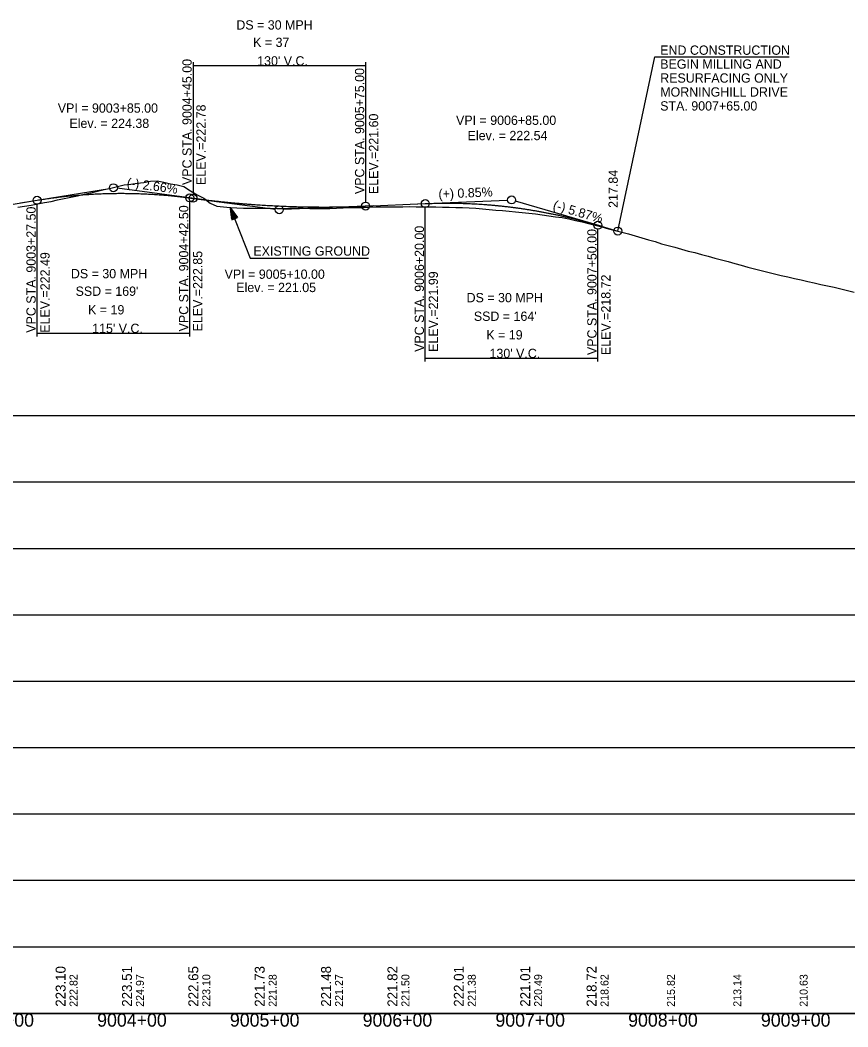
# Model space of a CAD drawing. Extents: x 69 to 2003113, y 512 to 837401.
# Drawn here: x 1878004 to 1878627, y 765979 to 766737 of the extents above; entities that cross this region are included whole.
import ezdxf

# ---------------------------------------------------------------- set-up
doc = ezdxf.new("R2010")
doc.units = 0
for name, color, linetype in [('BR_AUTO DIMENSION', 7, 'Continuous'), ('BR_CENTER LINE BASELINE', 7, 'Continuous'), ('BR_CONCRETE', 7, 'Continuous'), ('BR_GRID DOTS', 7, 'Continuous'), ('BR_GRID LINES', 7, 'Continuous'), ('BR_TEXT', 7, 'Continuous'), ('Default', 7, 'Continuous'), ('RD_HC_Points', 7, 'Continuous'), ('RD_PD_ALT1_TrvlWay', 7, 'Continuous'), ('RD_SHT_ID', 7, 'Continuous'), ('RD_SHT_IplotShp', 7, 'Continuous')]:
    doc.layers.add(name, color=color, linetype=linetype)

msp = doc.modelspace()

# ---------------------------------------------------------------- linework, layer by layer
at = {"layer": 'BR_AUTO DIMENSION'}
for p, q in [((1880911.61, 766439.14), (1877507.29, 766439.14)), ((1880911.61, 766389.14), (1877507.29, 766389.14)), ((1880911.61, 766339.14), (1877507.29, 766339.14)), ((1880911.61, 766289.14), (1877507.29, 766289.14)), ((1880911.61, 766239.14), (1877507.29, 766239.14)), ((1880911.61, 766189.14), (1877507.29, 766189.14)), ((1880911.61, 766139.14), (1877507.29, 766139.14)), ((1880911.61, 766089.14), (1877507.29, 766089.14)), ((1880911.61, 766039.14), (1877507.29, 766039.14)), ((1880911.61, 765989.14), (1877507.29, 765989.14))]:
    msp.add_line(p, q, dxfattribs=at)
at = {"layer": 'BR_CENTER LINE BASELINE'}
for p, q in [((1878003.69, 766599.52), (1878070.79, 766610.55)), ((1878144.13, 766601.67), (1878076.73, 766610.64)), ((1878128.37, 766603.77), (1878195.78, 766594.8)), ((1878302.82, 766598.83), (1878370.76, 766601.71)), ((1878441.88, 766581.83), (1878376.63, 766600.99)), ((1878269.69, 766597.42), (1878201.75, 766594.54))]:
    msp.add_line(p, q, dxfattribs=at)
for centre in [(1878073.75, 766611.03), (1878373.75, 766601.84), (1878198.75, 766594.41), (1878453.75, 766578.34)]:
    msp.add_circle(centre, 3, dxfattribs=at)
at = {"layer": 'BR_GRID DOTS'}
for p, q in [((1878453.75, 766578.34), (1878481.71, 766709.65)), ((1878133.75, 766705.55), (1878133.75, 766606.05)), ((1878133.75, 766703.05), (1878263.75, 766703.05)), ((1878263.75, 766705.55), (1878263.75, 766600.17)), ((1878016.25, 766499.09), (1878016.25, 766598.59)), ((1878131.25, 766499.09), (1878131.25, 766600.39)), ((1878308.75, 766480.24), (1878308.75, 766596.08)), ((1878438.75, 766480.24), (1878438.75, 766579.74)), ((1878016.25, 766501.59), (1878131.25, 766501.59)), ((1878308.75, 766482.74), (1878438.75, 766482.74))]:
    msp.add_line(p, q, dxfattribs=at)
msp.add_lwpolyline([(1878481.71, 766709.65), (1878582.93, 766709.65)], dxfattribs=at)
for centre in [(1878016.25, 766601.59), (1878131.25, 766603.39), (1878133.75, 766603.05), (1878308.75, 766599.08), (1878263.75, 766597.17), (1878438.75, 766582.74)]:
    msp.add_circle(centre, 3, dxfattribs=at)
at = {"layer": 'BR_GRID LINES'}
for p, q in [((1877993.75, 766597.89), (1878016.25, 766601.59)), ((1878131.25, 766603.39), (1878133.75, 766603.05)), ((1878263.75, 766597.17), (1878308.75, 766599.08)), ((1878438.75, 766582.74), (1878453.75, 766578.34))]:
    msp.add_line(p, q, dxfattribs=at)
for points in [[(1878016.25, 766601.59), (1878018.55, 766601.96), (1878020.85, 766602.31), (1878023.15, 766602.66), (1878025.45, 766602.99), (1878027.75, 766603.3), (1878030.05, 766603.61), (1878032.35, 766603.9), (1878034.65, 766604.17), (1878036.95, 766604.43), (1878039.25, 766604.68), (1878041.55, 766604.92), (1878043.85, 766605.14), (1878046.15, 766605.34), (1878048.45, 766605.54), (1878050.75, 766605.72), (1878053.05, 766605.88), (1878055.35, 766606.03), (1878057.65, 766606.17), (1878059.95, 766606.3), (1878062.25, 766606.41), (1878064.55, 766606.51), (1878066.85, 766606.59), (1878069.15, 766606.66), (1878071.45, 766606.72), (1878073.75, 766606.76), (1878076.05, 766606.79), (1878078.35, 766606.81), (1878080.65, 766606.81), (1878082.95, 766606.79), (1878085.25, 766606.77), (1878087.55, 766606.73), (1878089.85, 766606.68), (1878092.15, 766606.61), (1878094.45, 766606.53), (1878096.75, 766606.44), (1878099.05, 766606.33), (1878101.35, 766606.21), (1878103.65, 766606.07), (1878105.95, 766605.92), (1878108.25, 766605.76), (1878110.55, 766605.59), (1878112.85, 766605.4), (1878115.15, 766605.19), (1878117.45, 766604.98), (1878119.75, 766604.74), (1878122.05, 766604.5), (1878124.35, 766604.24), (1878126.65, 766603.97), (1878128.95, 766603.69), (1878131.25, 766603.39)], [(1878133.75, 766603.05), (1878136.35, 766602.71), (1878138.95, 766602.38), (1878141.55, 766602.06), (1878144.15, 766601.74), (1878146.75, 766601.44), (1878149.35, 766601.14), (1878151.95, 766600.86), (1878154.55, 766600.58), (1878157.15, 766600.31), (1878159.75, 766600.05), (1878162.35, 766599.8), (1878164.95, 766599.56), (1878167.55, 766599.33), (1878170.15, 766599.11), (1878172.75, 766598.89), (1878175.35, 766598.69), (1878177.95, 766598.49), (1878180.55, 766598.31), (1878183.15, 766598.13), (1878185.75, 766597.96), (1878188.35, 766597.8), (1878190.95, 766597.65), (1878193.55, 766597.51), (1878196.15, 766597.38), (1878198.75, 766597.26), (1878201.35, 766597.15), (1878203.95, 766597.04), (1878206.55, 766596.95), (1878209.15, 766596.86), (1878211.75, 766596.78), (1878214.35, 766596.72), (1878216.95, 766596.66), (1878219.55, 766596.61), (1878222.15, 766596.57), (1878224.75, 766596.54), (1878227.35, 766596.52), (1878229.95, 766596.5), (1878232.55, 766596.5), (1878235.15, 766596.5), (1878237.75, 766596.52), (1878240.35, 766596.54), (1878242.95, 766596.58), (1878245.55, 766596.62), (1878248.15, 766596.67), (1878250.75, 766596.73), (1878253.35, 766596.8), (1878255.95, 766596.88), (1878258.55, 766596.96), (1878261.15, 766597.06), (1878263.75, 766597.17)], [(1878308.75, 766599.08), (1878311.35, 766599.18), (1878313.95, 766599.26), (1878316.55, 766599.33), (1878319.15, 766599.38), (1878321.75, 766599.41), (1878324.35, 766599.42), (1878326.95, 766599.42), (1878329.55, 766599.4), (1878332.15, 766599.36), (1878334.75, 766599.31), (1878337.35, 766599.23), (1878339.95, 766599.14), (1878342.55, 766599.03), (1878345.15, 766598.91), (1878347.75, 766598.77), (1878350.35, 766598.61), (1878352.95, 766598.43), (1878355.55, 766598.23), (1878358.15, 766598.02), (1878360.75, 766597.79), (1878363.35, 766597.54), (1878365.95, 766597.27), (1878368.55, 766596.99), (1878371.15, 766596.69), (1878373.75, 766596.37), (1878376.35, 766596.04), (1878378.95, 766595.69), (1878381.55, 766595.31), (1878384.15, 766594.93), (1878386.75, 766594.52), (1878389.35, 766594.1), (1878391.95, 766593.66), (1878394.55, 766593.2), (1878397.15, 766592.73), (1878399.75, 766592.23), (1878402.35, 766591.72), (1878404.95, 766591.2), (1878407.55, 766590.65), (1878410.15, 766590.09), (1878412.75, 766589.51), (1878415.35, 766588.91), (1878417.95, 766588.29), (1878420.55, 766587.66), (1878423.15, 766587.01), (1878425.75, 766586.34), (1878428.35, 766585.66), (1878430.95, 766584.96), (1878433.55, 766584.24), (1878436.15, 766583.5), (1878438.75, 766582.74)]]:
    msp.add_spline(points, degree=3, dxfattribs=at)
at = {"layer": 'BR_TEXT'}
for points in [[(1878001.79, 766596.29), (1878006.79, 766597.13), (1878011.79, 766597.96), (1878016.79, 766598.87), (1878021.79, 766599.81), (1878026.79, 766600.74), (1878031.79, 766601.78), (1878036.79, 766602.84), (1878041.79, 766603.89), (1878046.79, 766604.95), (1878051.79, 766606.09), (1878056.79, 766607.25), (1878061.79, 766608.42), (1878066.79, 766609.65), (1878071.79, 766610.8), (1878076.79, 766611.99), (1878081.79, 766613.15), (1878086.79, 766613.74), (1878091.79, 766614.35), (1878096.79, 766615.02), (1878101.79, 766615.85), (1878106.79, 766616.17), (1878111.79, 766615.18), (1878116.79, 766613.94), (1878121.79, 766613.2), (1878126.79, 766612), (1878131.79, 766608.74), (1878136.79, 766605.58), (1878141.79, 766603.15), (1878146.79, 766599.49), (1878151.79, 766597.22), (1878156.79, 766596.53), (1878161.79, 766596.04), (1878166.79, 766595.84), (1878171.79, 766595.64), (1878176.79, 766595.62), (1878181.79, 766595.67), (1878186.79, 766595.6), (1878191.79, 766595.52), (1878196.79, 766595.45), (1878201.79, 766595.46), (1878206.79, 766595.59), (1878211.79, 766595.62), (1878216.79, 766595.53), (1878221.79, 766595.43), (1878226.79, 766595.38), (1878231.79, 766595.38), (1878236.79, 766595.37), (1878241.79, 766595.66), (1878246.79, 766595.97), (1878251.79, 766596.09), (1878256.79, 766596.06)], [(1878256.79, 766596.06), (1878261.79, 766596.03), (1878266.79, 766596.31), (1878271.79, 766596.56), (1878276.79, 766596.54), (1878281.79, 766596.51), (1878286.79, 766596.62), (1878291.79, 766596.75), (1878296.79, 766596.79), (1878301.79, 766596.69), (1878306.79, 766596.59), (1878311.79, 766596.67), (1878316.79, 766596.57), (1878321.79, 766596.41), (1878326.79, 766596.28), (1878331.79, 766596.18), (1878336.79, 766596.08), (1878341.79, 766595.94), (1878346.79, 766595.72), (1878351.79, 766595.2), (1878356.79, 766594.68), (1878361.79, 766594.17), (1878366.79, 766593.81), (1878371.79, 766593.46), (1878376.79, 766592.9), (1878381.79, 766592.31), (1878386.79, 766591.78), (1878391.79, 766591.27), (1878396.79, 766590.66), (1878401.79, 766589.83), (1878406.79, 766589.08), (1878411.79, 766588.57), (1878416.79, 766587.52), (1878421.79, 766586.3), (1878426.79, 766585.22), (1878431.79, 766584.07), (1878436.79, 766582.78), (1878441.79, 766581.48), (1878446.79, 766580.17), (1878451.79, 766578.85), (1878456.79, 766577.54), (1878461.79, 766576.18), (1878466.79, 766574.71), (1878471.79, 766573.26), (1878476.79, 766571.83), (1878481.79, 766570.4), (1878486.79, 766568.76), (1878491.79, 766567.43), (1878496.79, 766566.14), (1878501.79, 766564.72), (1878506.79, 766563.36), (1878511.79, 766562.12), (1878516.79, 766560.84), (1878521.79, 766559.43), (1878526.79, 766558.03), (1878531.79, 766556.69), (1878536.79, 766555.38), (1878541.79, 766554.05), (1878546.79, 766552.65), (1878551.79, 766551.25), (1878556.79, 766549.86), (1878561.79, 766548.58), (1878566.79, 766547.35), (1878571.79, 766546.16), (1878576.79, 766545.02), (1878581.79, 766543.88), (1878586.79, 766542.74), (1878591.79, 766541.61), (1878596.79, 766540.47), (1878601.79, 766539.34), (1878606.79, 766538.2), (1878611.79, 766537.1), (1878616.79, 766536.04), (1878621.79, 766534.91), (1878626.79, 766533.69), (1878631.79, 766532.47)]]:
    msp.add_lwpolyline(points, dxfattribs=at)
at = {"layer": 'Default'}
msp.add_line((1877688.75, 765989.14), (1880688.75, 765989.14), dxfattribs=at)
at = {"layer": 'RD_PD_ALT1_TrvlWay'}
for p, q in [((1878161.79, 766596.04), (1878176.76, 766558.09)), ((1878165.09, 766587.67), (1878161.79, 766596.04)), ((1878161.79, 766596.04), (1878167.19, 766588.49)), ((1878161.79, 766596.04), (1878163, 766586.84)), ((1878163, 766586.84), (1878167.19, 766588.49)), ((1878176.76, 766558.09), (1878265.94, 766558.09))]:
    msp.add_line(p, q, dxfattribs=at)
for points in [[(1878164.99, 766587.75), (1878161.92, 766595.55), (1878164.96, 766587.68), (1878161.99, 766595.15), (1878164.86, 766587.68), (1878162.02, 766594.88), (1878164.75, 766587.65), (1878162.05, 766594.56), (1878164.67, 766587.6), (1878162.12, 766594.06), (1878164.56, 766587.54), (1878162.21, 766593.54), (1878164.44, 766587.53), (1878162.27, 766593.14), (1878164.36, 766587.48), (1878162.33, 766592.68), (1878164.25, 766587.5), (1878162.38, 766592.29), (1878164.19, 766587.39), (1878162.42, 766591.94), (1878164.06, 766587.38), (1878162.48, 766591.44), (1878163.96, 766587.32), (1878162.59, 766590.85), (1878163.86, 766587.26), (1878162.6, 766590.43), (1878163.76, 766587.22), (1878162.68, 766589.8), (1878163.64, 766587.22), (1878162.78, 766589.3), (1878163.54, 766587.12), (1878162.83, 766588.86), (1878163.44, 766587.12), (1878162.87, 766588.46), (1878163.36, 766587.02), (1878162.95, 766587.96), (1878163.24, 766587.06), (1878163.02, 766587.41), (1878163.13, 766587.05)], [(1878162.07, 766595.52), (1878165.11, 766587.8), (1878162.23, 766595.27), (1878165.22, 766587.84), (1878162.38, 766595.03), (1878165.3, 766587.83), (1878162.57, 766594.82), (1878165.36, 766587.88), (1878162.77, 766594.56), (1878165.46, 766587.89), (1878162.95, 766594.31), (1878165.53, 766587.92), (1878163.16, 766594.01), (1878165.62, 766587.94), (1878163.41, 766593.65), (1878165.73, 766588), (1878163.61, 766593.33), (1878165.82, 766587.99), (1878163.84, 766593), (1878165.9, 766588.05), (1878164.08, 766592.7), (1878165.98, 766588.08), (1878164.32, 766592.35), (1878166.03, 766588.16), (1878164.64, 766591.89), (1878166.13, 766588.16), (1878164.87, 766591.61), (1878166.21, 766588.15), (1878165.17, 766591.22), (1878166.29, 766588.22), (1878165.41, 766590.81), (1878166.38, 766588.28), (1878165.63, 766590.5), (1878166.47, 766588.37), (1878165.88, 766590.22), (1878166.54, 766588.4), (1878166.16, 766589.75), (1878166.69, 766588.38), (1878166.35, 766589.49), (1878166.82, 766588.43), (1878166.54, 766589.32), (1878166.93, 766588.57), (1878167.05, 766588.52), (1878166.89, 766588.56)]]:
    msp.add_lwpolyline(points, dxfattribs=at)

# ---------------------------------------------------------------- texts
at = {"layer": 'BR_CENTER LINE BASELINE'}
for s, rotation, p in [('(-) 2.66%', 352.4233, (1878083.61, 766611.5)), ('(+) 0.85%', 2.43062, (1878318.79, 766602.76)), ('(-) 5.87%', 343.63166, (1878404.34, 766594.94))]:
    msp.add_text(s, height=7, rotation=rotation, dxfattribs=at).set_placement(p)
at = {"layer": 'BR_CONCRETE'}
for s, height, p in [('VPC STA. 9004+45.00 ', 7, (1878132.75, 766613.05)), ('VPC STA. 9005+75.00 ', 7, (1878262.75, 766606.22)), ('ELEV.=222.78', 7, (1878143.25, 766613.05)), ('ELEV.=221.60', 7, (1878273.25, 766606.22)), ('VPC STA. 9003+27.50 ', 7, (1878015.25, 766501.81)), ('VPC STA. 9004+42.50 ', 7, (1878130.25, 766502.81)), ('VPC STA. 9006+20.00 ', 7, (1878307.75, 766487.39)), ('VPC STA. 9007+50.00 ', 7, (1878437.75, 766484.98)), ('ELEV.=222.85', 7, (1878140.75, 766502.81)), ('ELEV.=222.49', 7, (1878025.75, 766501.81)), ('ELEV.=221.99', 7, (1878318.25, 766487.39)), ('ELEV.=218.72', 7, (1878448.25, 766484.98)), ('222.82', 6, (1878046.75, 765994.14)), ('224.97', 6, (1878096.75, 765994.14)), ('223.10', 6, (1878146.75, 765994.14)), ('221.28', 6, (1878196.75, 765994.14)), ('221.27', 6, (1878246.75, 765994.14)), ('221.50', 6, (1878296.75, 765994.14)), ('221.38', 6, (1878346.75, 765994.14)), ('220.49', 6, (1878396.75, 765994.14)), ('218.62', 6, (1878446.75, 765994.14)), ('215.82', 6, (1878496.75, 765994.14)), ('213.14', 6, (1878546.75, 765994.14)), ('210.63', 6, (1878596.75, 765994.14))]:
    msp.add_text(s, height=height, rotation=90, dxfattribs=at).set_placement(p)
at = {"layer": 'BR_GRID DOTS'}
for s, p in [('DS = 30 MPH', (1878166.4, 766730.14)), ('K = 37', (1878179.03, 766717.05)), ("130' V.C.", (1878182.11, 766703.05)), ('DS = 30 MPH', (1878041.76, 766542.83)), ("SSD = 169'", (1878045.3, 766529.59)), ('DS = 30 MPH', (1878339.85, 766524.75)), ('K = 19', (1878054.72, 766515.59)), ("SSD = 164'", (1878345.3, 766510.74)), ("115' V.C.", (1878057.78, 766501.59)), ('K = 19', (1878354.72, 766496.74)), ("130' V.C.", (1878357.11, 766482.74))]:
    msp.add_text(s, height=7, dxfattribs=at).set_placement(p)
at = {"layer": 'RD_HC_Points'}
for s, p in [('223.10', (1878037.75, 765994.14)), ('223.51', (1878087.75, 765994.14)), ('222.65', (1878137.75, 765994.14)), ('221.73', (1878187.75, 765994.14)), ('221.48', (1878237.75, 765994.14)), ('221.82', (1878287.75, 765994.14)), ('222.01', (1878337.75, 765994.14)), ('221.01', (1878387.75, 765994.14)), ('218.72', (1878437.75, 765994.14))]:
    msp.add_text(s, height=7.5, rotation=90, dxfattribs=at).set_placement(p)
at = {"layer": 'RD_PD_ALT1_TrvlWay'}
msp.add_text('EXISTING GROUND', height=7, dxfattribs=at).set_placement((1878179.22, 766559.82))
at = {"layer": 'RD_SHT_ID'}
for s, p in [('9003+00', (1877961.54, 765979.14)), ('9004+00', (1878061.54, 765979.14)), ('9005+00', (1878161.54, 765979.14)), ('9006+00', (1878261.54, 765979.14)), ('9007+00', (1878361.54, 765979.14)), ('9008+00', (1878461.54, 765979.14)), ('9009+00', (1878561.54, 765979.14))]:
    msp.add_text(s, height=10, dxfattribs=at).set_placement(p)
at = {"layer": 'RD_SHT_IplotShp'}
for s, p in [('END CONSTRUCTION', (1878485.7, 766711.15)), ('BEGIN MILLING AND', (1878485.7, 766700.65)), ('RESURFACING ONLY', (1878485.7, 766690.15)), ('MORNINGHILL DRIVE ', (1878485.7, 766679.65)), ('VPI = 9003+85.00', (1878031.89, 766667.53)), ('STA. 9007+65.00', (1878485.7, 766669.15)), ('Elev. = 224.38', (1878040.65, 766656.03)), ('VPI = 9006+85.00', (1878331.89, 766658.34)), ('Elev. = 222.54', (1878340.63, 766646.84)), ('VPI = 9005+10.00', (1878157.57, 766542.41)), ('Elev. = 221.05', (1878166.35, 766532.41))]:
    msp.add_text(s, height=7, dxfattribs=at).set_placement(p)
msp.add_text('217.84', height=7, rotation=90, dxfattribs=at).set_placement((1878453.75, 766595.84))

doc.saveas('drawing.dxf')
